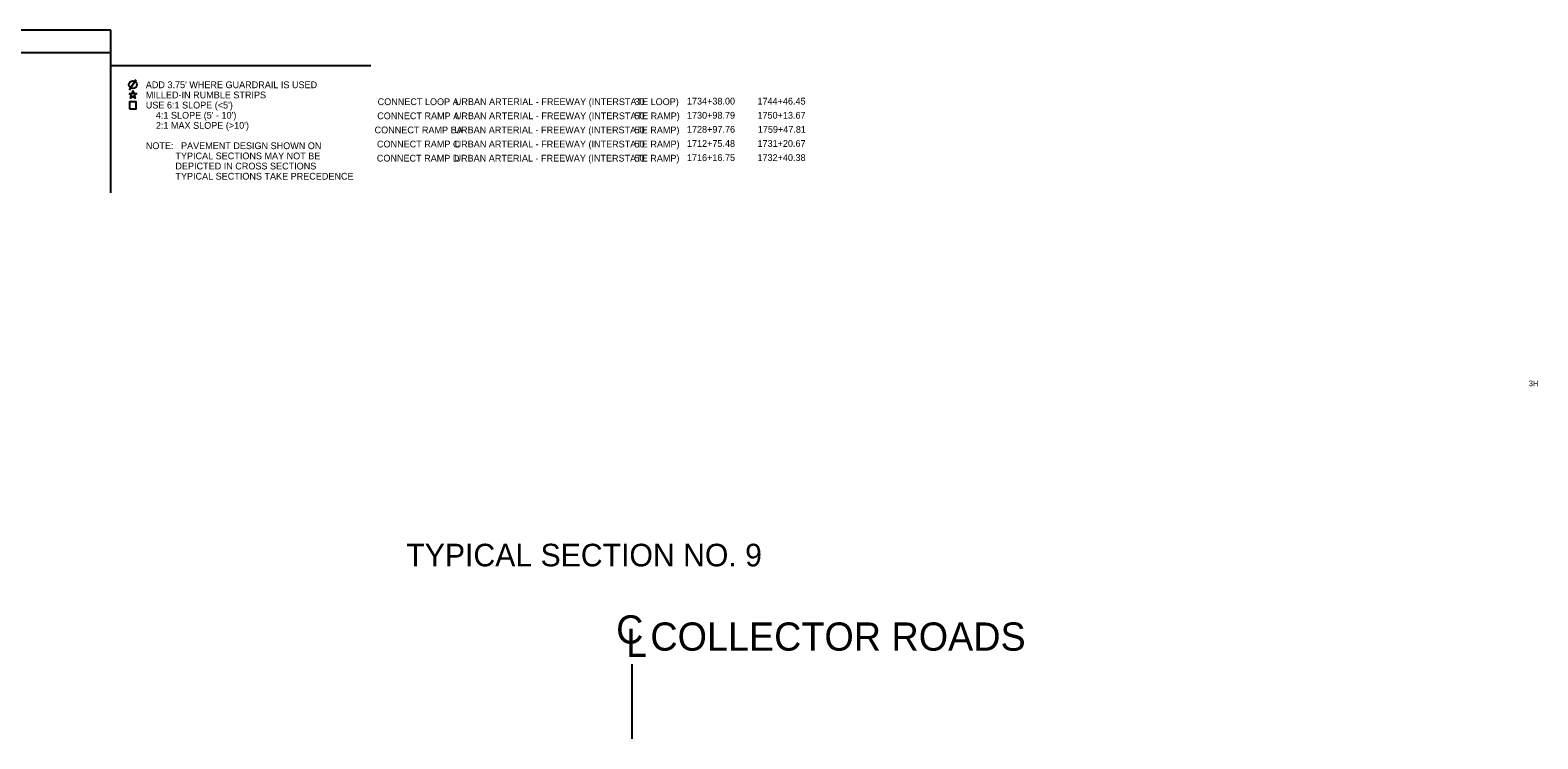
# Model space of a CAD drawing. Extents: x 2003207 to 2014043, y 843846 to 860154.
# Drawn here: x 2013648.6 to 2013782.1, y 844037.6 to 844100.4 of the extents above; entities that cross this region are included whole.
import ezdxf

# ---------------------------------------------------------------- set-up
doc = ezdxf.new("R2010")
doc.units = 0
for name, color, linetype in [('RD_EX_Road_txCode', 7, 'Continuous'), ('RD_SHT_Bndy', 7, 'Continuous'), ('RD_SHT_TX', 7, 'Continuous'), ('RD_TX_Misc1', 7, 'Continuous'), ('RD_TX_TypSect', 7, 'Continuous')]:
    doc.layers.add(name, color=color, linetype=linetype)

msp = doc.modelspace()

# ---------------------------------------------------------------- linework, layer by layer
at = {"layer": 'RD_EX_Road_txCode'}
msp.add_line((2013657.38, 844095.11), (2013657.95, 844096.05), dxfattribs=at)
for points in [[(2013657.33, 844094.79), (2013657.59, 844094.79), (2013657.67, 844095.03), (2013657.75, 844094.79), (2013658, 844094.79), (2013657.79, 844094.64), (2013657.87, 844094.4), (2013657.67, 844094.54), (2013657.46, 844094.4), (2013657.54, 844094.64)], [(2013657.37, 844093.45), (2013657.97, 844093.45), (2013657.97, 844094.05), (2013657.37, 844094.05)]]:
    msp.add_lwpolyline(points, close=True, dxfattribs=at)
msp.add_circle((2013657.67, 844095.58), 0.35, dxfattribs=at)
at = {"layer": 'RD_SHT_Bndy'}
for p, q in [((2013655.72, 844100.41), (2013615.72, 844100.41)), ((2013655.72, 844098.41), (2013655.72, 844100.41)), ((2013655.72, 844098.41), (2013615.72, 844098.41)), ((2013655.72, 844085.99), (2013655.72, 844098.41)), ((2013678.75, 844097.24), (2013655.75, 844097.24))]:
    msp.add_line(p, q, dxfattribs=at)
at = {"layer": 'RD_TX_TypSect'}
msp.add_line((2013701.89, 844037.63), (2013701.89, 844044.25), dxfattribs=at)

# ---------------------------------------------------------------- texts
at = {"layer": 'RD_EX_Road_txCode'}
for s, p in [("ADD 3.75' WHERE GUARDRAIL IS USED", (2013658.81, 844095.27)), ('MILLED-IN RUMBLE STRIPS', (2013658.81, 844094.37)), ("USE 6:1 SLOPE (<5')", (2013658.81, 844093.47)), ("    4:1 SLOPE (5' - 10')", (2013658.81, 844092.57)), ("    2:1 MAX SLOPE (>10')", (2013658.81, 844091.67)), ('NOTE:   PAVEMENT DESIGN SHOWN ON', (2013658.81, 844089.87)), (' TYPICAL SECTIONS MAY NOT BE ', (2013661.21, 844088.97)), (' DEPICTED IN CROSS SECTIONS', (2013661.21, 844088.07)), (' TYPICAL SECTIONS TAKE PRECEDENCE', (2013661.21, 844087.17))]:
    msp.add_text(s, height=0.6, dxfattribs=at).set_placement(p)
at = {"layer": 'RD_SHT_TX'}
for s, height, p in [('CONNECT LOOP A', 0.6, (2013679.35, 844093.77)), ('URBAN ARTERIAL - FREEWAY (INTERSTATE LOOP)', 0.6, (2013686.19, 844093.77)), ('30', 0.6, (2013702.11, 844093.77)), ('1734+38.00', 0.6, (2013706.75, 844093.82)), ('1744+46.45', 0.6, (2013713, 844093.82)), ('CONNECT RAMP A', 0.6, (2013679.31, 844092.52)), ('URBAN ARTERIAL - FREEWAY (INTERSTATE RAMP)', 0.6, (2013686.19, 844092.52)), ('50', 0.6, (2013702.11, 844092.52)), ('1730+98.79', 0.6, (2013706.75, 844092.57)), ('1750+13.67', 0.6, (2013713, 844092.57)), ('CONNECT RAMP BA', 0.6, (2013679.08, 844091.27)), ('URBAN ARTERIAL - FREEWAY (INTERSTATE RAMP)', 0.6, (2013686.16, 844091.27)), ('50', 0.6, (2013702.11, 844091.27)), ('1728+97.76', 0.6, (2013706.75, 844091.32)), ('1759+47.81', 0.6, (2013713.03, 844091.32)), ('CONNECT RAMP C', 0.6, (2013679.29, 844090.02)), ('URBAN ARTERIAL - FREEWAY (INTERSTATE RAMP)', 0.6, (2013686.17, 844090.02)), ('50', 0.6, (2013702.11, 844090.02)), ('1712+75.48', 0.6, (2013706.75, 844090.07)), ('1731+20.67', 0.6, (2013713, 844090.07)), ('CONNECT RAMP D', 0.6, (2013679.28, 844088.77)), ('URBAN ARTERIAL - FREEWAY (INTERSTATE RAMP)', 0.6, (2013686.16, 844088.77)), ('50', 0.6, (2013702.11, 844088.77)), ('1716+16.75', 0.6, (2013706.75, 844088.82)), ('1732+40.38', 0.6, (2013713, 844088.82)), ('3H', 0.5, (2013781.33, 844068.87))]:
    msp.add_text(s, height=height, dxfattribs=at).set_placement(p)
at = {"layer": 'RD_TX_Misc1'}
for s, p in [('C', (2013700.48, 844046.07)), ('L', (2013701.36, 844044.89)), ('COLLECTOR ROADS', (2013703.51, 844045.44))]:
    msp.add_text(s, height=2.5, dxfattribs=at).set_placement(p)
at = {"layer": 'RD_TX_TypSect'}
msp.add_text('TYPICAL SECTION NO. 9', height=2, dxfattribs=at).set_placement((2013681.89, 844052.91))

doc.saveas('drawing.dxf')
